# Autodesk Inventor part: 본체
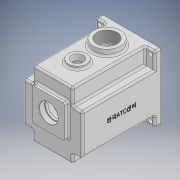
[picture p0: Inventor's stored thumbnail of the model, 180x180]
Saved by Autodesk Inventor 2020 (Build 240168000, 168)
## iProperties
Created: 2022-01
Part Number: 본체
Material: 일반
Document SubType Name: Modeling
Designer: user
Density: 1 g/cm^3
Appearance: 기본값
Mass: 519.717 g
Surface Area: 1171.01 cm^2
Volume: 519.717 cm^3
Author: user
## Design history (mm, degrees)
sketch "스케치1"
  geometry: L1 (-49, -55)-(49, -55); L2 (49, -55)-(49, 55); L3 (49, 55)-(-49, 55); L4 (-49, 55)-(-49, -55); L5 (-49, -55)-(49, 55); L6 (49, -55)-(-49, 55); 1 further point
  constraints: 12 end point, 2 midpoint, 2 parallel, 1 horizontal, 1 perpendicular
  dimensions: "d0" = 98 distance of L3.end L2.end; "d1" = 110 distance of L2.end L1.end
extrude "돌출1" new body sketch "스케치1" stored distance "d2" = 130; taper "d3" = 0 deg
sketch "스케치2"
  geometry: L1 (49, -55)-(49, 55) reference; L2 (49, 55)-(33, 55); L3 (33, 55)-(33, 28); L4 (33, 28)-(49, 28); L5 (49, 28)-(49, 55); L6 (49, -55)-(33, -55); L7 (33, -55)-(33, -38); L8 (33, -38)-(49, -38); L9 (49, -38)-(49, -55); L10 (49, 55)-(-49, 55) reference; L11 (-49, 55)-(-33, 55); L12 (-33, 55)-(-33, 28); L13 (-33, 28)-(-49, 28); L14 (-49, 28)-(-49, 55); L15 (-49, 55)-(-49, -55) reference; L16 (-49, -55)-(-33, -55); L17 (-33, -55)-(-33, -38); L18 (-33, -38)-(-49, -38); L19 (-49, -38)-(-49, -55); 5 further points
  constraints: 32 end point, 8 parallel, 4 horizontal, 4 perpendicular
  dimensions: "d4" = 27 distance of L3.end L2.end; "d5" = 16 distance of L1.end L2.end; "d6" = 17 distance of L6.end L7.end; "d7" = 16 distance of L7.end L8.end; "d8" = 16 distance of L12.end L13.end; "d9" = 27 distance of L11.end L12.end; "d10" = 16 distance of L18.end L17.end; "d11" = 17 distance of L17.end L16.end
extrude "돌출2" cut sketch "스케치2" distance "d12" = 120; taper "d13" = 0 deg
node "작업 평면1"
sketch "스케치4"
  geometry: L1 (0, 0)-(98, 0) reference; L2 (49, 0)-(49, -40); L3 (49, -40)-(49, -89); C1 r 22.5 at (49, -40); C2 r 15 at (49, -89); 1 further point
  constraints: 4 end point, 2 centre point, 2 coincident, 2 vertical, 1 midpoint
  dimensions: "d19" = 40 distance of L2.start L2.end; "d20" = 45 diameter of C1; "d21" = 49 distance of L3.start L3.end; "d22" = 30 diameter of C2
extrude "돌출4" join sketch "스케치4" distance "d23" = 10; taper "d24" = 0 deg
extrude "돌출5" join sketch "스케치4" distance "d25" = 5; taper "d26" = 0 deg
sketch "스케치6"
  geometry: L1 (0, 0)-(0, 6); L2 (-27, -21)-(27, -21); L3 (27, -21)-(27, 33); L4 (27, 33)-(-27, 33); L5 (-27, 33)-(-27, -21); L6 (-27, -21)-(27, 33); L7 (27, -21)-(-27, 33); L8 (-33, -55)-(33, -55) reference; C1 r 16 at (0, 6)
  constraints: 14 end point, 2 midpoint, 2 parallel, 1 centre point, 1 coincident, 1 horizontal, 1 perpendicular, 1 vertical
  dimensions: "d39" = 32 diameter of C1; "d40" = 54 distance of L4.end L3.end; "d41" = 54 distance of L3.end L2.end; "d178" = 61 distance from line of L1.end L8
extrude "돌출8" join sketch "스케치6" distance "d42" = 7; taper "d43" = 0 deg
sketch "스케치7"
  geometry: L1 (27, 33)-(-27, 33) reference; L2 (0, 33)-(0, 6); C1 r 16 at (0, 6); 1 further point
  constraints: 2 end point, 1 centre point, 1 coincident, 1 midpoint, 1 vertical
  dimensions: "d44" = 27 distance of L2.start L2.end; "d45" = 32 diameter of C1
extrude "돌출9" cut sketch "스케치7" distance "d46" = 0.8; taper "d47" = -30 deg
sketch "스케치8"
  geometry: C1 r 15.538 at (0, 0) reference; 1 further point
extrude "돌출10" cut sketch "스케치8" distance "d48" = 8.3; taper "d49" = 0 deg
sketch "스케치16"
  geometry: C1 r 22.5 at (0, 0) reference; 2 further points
  constraints: 1 coincident
hole "구멍3" sketch "스케치16" at (0, 0) diameter "d76" = 33.376; stored, may be unused: countersink angle "d80" = 90 deg, drill point angle "d82" = 0 deg; dims "d77" = 19, "d78" = 22, "d79" = 7, "d81" = 22
sketch "스케치18"
  geometry: C1 r 15 at (0, 0) reference; 2 further points
  constraints: 1 coincident
hole "구멍4" sketch "스케치18" at (0, 0) diameter "d87" = 20; stored, may be unused: countersink angle "d91" = 90 deg, drill point angle "d93" = 0 deg; dims "d88" = 19, "d89" = 22, "d90" = 7, "d92" = 20
sketch "스케치19"
  geometry: L1 (33, 55)-(49, 55) reference; L2 (49, 55)-(49, 28) reference; L3 (0, 0)-(0, 87.933); L4 (0, 0)-(72.07, 0); C1 r 3.5 at (42, 48); C2 r 3.5 at (-42, 48); C3 r 3.5 at (-42, -48); C4 r 3.5 at (42, -48)
  constraints: 4 centre point, 4 end point, 3 symmetric about line, 1 horizontal, 1 vertical, 3 other
  dimensions: "d94" = 7 diameter of C1; "d95" = 7 distance from line of L1 C1.centre; "d96" = 7 distance from line of L2 C1.centre
extrude "돌출14" cut sketch "스케치19" distance "d97" = 10; taper "d98" = 0 deg
sketch "스케치21"
  geometry: L1 (33, -55)-(-33, -55) reference; L2 (0, -55)-(0, -5); L3 (0, -5)-(0, 45); L4 (0, 45)-(23, 45); L5 (0, 45)-(-23, 45); L6 (-23, 45)-(-23, 22.354); L7 (23, 45)-(23, 18.054); C1 r 42 at (0, -5); 3 further points
  constraints: 12 end point, 4 vertical, 2 horizontal, 1 centre point, 1 coincident, 1 midpoint
  dimensions: "d102" = 50 distance of L2.start L2.end; "d103" = 84 diameter of C1; "d104" = 50 distance of L3.start L3.end; "d105" = 23 distance of L3.end L4.end; "d106" = 23 distance of L3.end L5.end
extrude "돌출15" cut sketch "스케치21" distance "d107" = 121; taper "d108" = 0 deg
sketch "스케치22"
  geometry: L1 (0, 0)-(0, 6); L2 (0, 0)-(0, -25); C1 r 16 at (0, 6) reference; C2 r 21 at (0, 6); C3 r 15 at (0, -25); 2 further points
  constraints: 4 end point, 2 centre point, 2 coincident, 2 vertical
  dimensions: "d109" = 6 distance of L1.start L1.end (derived); "d110" = 42 diameter of C2; "d111" = 25 distance of L1.start L2.end; "d112" = 30 diameter of C3
extrude "돌출16" join sketch "스케치22" distance "d113" = 7; taper "d114" = 0 deg
sketch "스케치23"
  geometry: A1 r 15 centre (0, -25) between (-8.978, -12.984) and (8.978, -12.984) reference; 2 further points
  constraints: 1 coincident
hole "구멍5" sketch "스케치23" at (0, -25) diameter "d115" = 19; stored, may be unused: countersink angle "d119" = 90 deg, drill point angle "d121" = 0 deg; dims "d116" = 19, "d117" = 22, "d118" = 7, "d120" = 10
sketch "스케치24"
  geometry: A1 r 21 centre (0, 6) between (8.978, -12.984) and (-8.978, -12.984) reference; 2 further points
  constraints: 1 coincident
hole "구멍6" sketch "스케치24" at (0, 6) diameter "d122" = 35; stored, may be unused: countersink angle "d126" = 90 deg, drill point angle "d128" = 0 deg; dims "d123" = 19, "d124" = 22, "d125" = 7, "d127" = 10
sketch "스케치25"
  geometry: C1 r 15.538 at (0, 0) reference; 2 further points
  constraints: 1 coincident
hole "구멍7" sketch "스케치25" at (0, 0) diameter "d129" = 28; stored, may be unused: countersink angle "d133" = 90 deg, drill point angle "d135" = 0 deg; dims "d130" = 19, "d131" = 22, "d132" = 7, "d134" = 10
sketch "스케치26"
  geometry: C1 r 10 at (23, 89) reference; C2 r 15 at (23, 89); 1 further point
  constraints: 1 centre point, 1 coincident
  dimensions: "d136" = 30 diameter of C2
extrude "돌출17" cut sketch "스케치26" distance "d137" = 5; taper "d138" = 0 deg
sketch "스케치27"
  geometry: L1 (23, 45)-(23, 30.143) reference; L2 (-23, 45)-(23, 45) reference; L3 (-23, 30.143)-(-23, 45) reference; L4 (-26, 31.729)-(-26, 48); L5 (-26, 48)-(26, 48); L6 (26, 48)-(26, 31.729); A1 r 42 centre (0, -5) between (-23, 30.143) and (23, 30.143) reference; A2 r 45 centre (0, -5) between (-26, 31.729) and (26, 31.729); 1 further point
  constraints: 6 end point, 2 point on circle, 1 centre point, 3 other
  dimensions: "d139" = 3 distance between parallel lines of L1 L6
extrude "돌출18" cut sketch "스케치27" distance "d140" = 9; taper "d141" = 0 deg
sketch "스케치29" dims "d149" = 8, "d150" = 8
  geometry: L1 (0, -47)-(0, -5); L2 (35.778, -1.006)-(63.216, -1.006); L3 (35.521, -10.852)-(64.123, -10.852); L4 (-35.778, -1.006)-(-61.244, -1.006); L5 (-35.777, -9)-(-63.569, -9); A1 r 42 centre (0, -5) between (-23, 30.143) and (23, 30.143) reference; A2 r 36 centre (0, -5) between (-36, -5) and (36, -5); 4 further points
  constraints: 10 end point, 7 point on circle, 5 horizontal, 1 centre point, 1 coincident, 1 horizontal alignment, 1 vertical, 1 vertical alignment, 6 other
  dimensions: "d147" = 42 distance of L1.start L1.end; "d148" = 72 diameter of A2
fillet "모깎기1" dims "d151" = 3
fillet "모깎기2" dims "d152" = 3
fillet "모깎기3" dims "d153" = 3
sketch "스케치30"
  geometry: L1 (-130, 107)-(-130, 86) reference; L2 (-10, 83)-(-127, 83) reference; 3 further points
  constraints: 1 other
  dimensions: "d154" = 65 distance from line of L1 point (-65, 50); "d157" = 33 distance from line of point (-65, 50) L2
extrude "돌출20" join sketch "스케치29" distance "d155" = 112; taper "d156" = 0 deg
feature "엠보싱1" dims "d158" = 0.5, "d159" = 0
fillet "모깎기4" dims "d160" = 3
fillet "모깎기6" dims "d162" = 0.3
sketch "스케치31"
  geometry: A1 r 4 centre (-36, -5) between (-36, -9) and (-35.778, -1.006) reference; A2 r 4 centre (36, -5) between (35.778, -1.006) and (36, -9) reference; 3 further points
  constraints: 2 coincident
hole "구멍8" sketch "스케치31" at (-36, -5), (36, -5) diameter "d163" = 3.242; stored, may be unused: countersink angle "d167" = 90 deg, drill point angle "d169" = 118 deg; dims "d164" = 7, "d165" = 22, "d166" = 7, "d168" = 9
fillet "모깎기8" dims "d171" = 6
fillet "모깎기9" dims "d172" = 3
fillet "모깎기10" dims "d173" = 3
fillet "모깎기11" dims "d174" = 3
chamfer "모따기1" distance "d175" = 1; stored, may be unused: second distance "d176" = 2, angle "d177" = 45 deg
sketch "스케치32"
  geometry: 1 further point
fillet "모깎기12" dims "d179" = 3
fillet "모깎기13" dims "d180" = 3
fillet "모깎기14" dims "d181" = 3
node "솔리드1"
mirror "미러1"
feature "A9D066F2-1C7D-4E18-AEED-F7BC21143FA4" dims "d87" = 20, "d88" = 19, "d89" = 22, "d90" = 7, "d91" = 90 deg, "d92" = 20, "d93" = 0
other parameters: "d14" = 7
